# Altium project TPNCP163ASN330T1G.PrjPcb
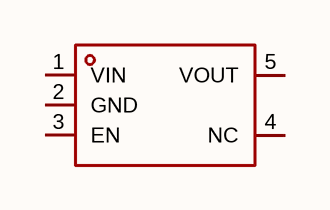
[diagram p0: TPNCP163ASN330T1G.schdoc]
1 sheet, 1 parts. Net scope: global (net labels, ports and power ports of the same name join across sheets).

## Sheet TPNCP163ASN330T1G.schdoc
size 127 x 101 mm

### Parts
U?  tpncp163asn330t1g  [SOT-23-5_L2.9-W1.6-P0.95-LS2.8-BR]  (value not drawn)

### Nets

Not connected (* = marked no-connect by the designer): U? 1(VIN) 2(GND) 3(EN) 4(NC) 5(VOUT)

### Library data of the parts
U? = tpncp163asn330t1g: 输出极性:正极;工作电压:6V;输出电压:3.3V;输出电流:250mA;电源纹波抑制比(PSRR):70dB@(1kHz);输出类型:固定;; Manufacturer: TECH PUBLIC(台舟); AddInBom: yes; ModelId: 7ba65df16e7b4570af156e925f9c37fe; ModelTransform: 114.173,114.173,0,90,0,0,0,0,0; Output Configuration: 正极; Voltage - Supply: 6V; Output Voltage: 3.3V; Output Current: 250mA; Voltage Dropout: 80mV@(200mA); standby current: 65uA; Output Type: 固定; Number of Outputs: 1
